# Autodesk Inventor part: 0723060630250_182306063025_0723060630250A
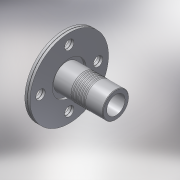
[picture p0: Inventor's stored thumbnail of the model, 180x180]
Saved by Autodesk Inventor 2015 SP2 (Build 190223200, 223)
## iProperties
Created: 2017-02
Part Number: 0723060630250_182306063025_0723060630250A
Material: PVC-Piping
Description: PLASSON FLANGE ADAPTOR WITH METAL FLANGE 63-2.1/2"
Document SubType Name: Modeling
Designer: KIM
Mass: 92.6774 g
Surface Area: 199.44 cm^2
Volume: 66.1981 cm^3
Density: 1.4 g/cm^3
Appearance: Smooth - White
Author: KIM
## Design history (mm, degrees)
derived "072306.ipt"
feature "Solid1::072306.ipt"
tag "TaggingFeature1"
body "Solid1"
other parameters: "d73" = 12.4, "d74" = 90 deg, "d75" = 0.3, "d76" = 185, "d77" = 18, "d78" = 72.5, "d80" = 0, "d82" = 360 deg, "d94" = 65, "d96" = 0.3, "d99" = 360 deg, "d101" = 63, "d102" = 44.1, "d103" = 124, "d104" = 1.26, "d107" = 81.9, "d108" = 3.1, "d109" = 61.74, "d110" = 49.6, "d111" = 6.3, "d115" = 6.3, "d_" = 63, "E_" = 82, "H_" = 124, "D_" = 185, "Dp_" = 145, "S_" = 18, "DN_" = 65
